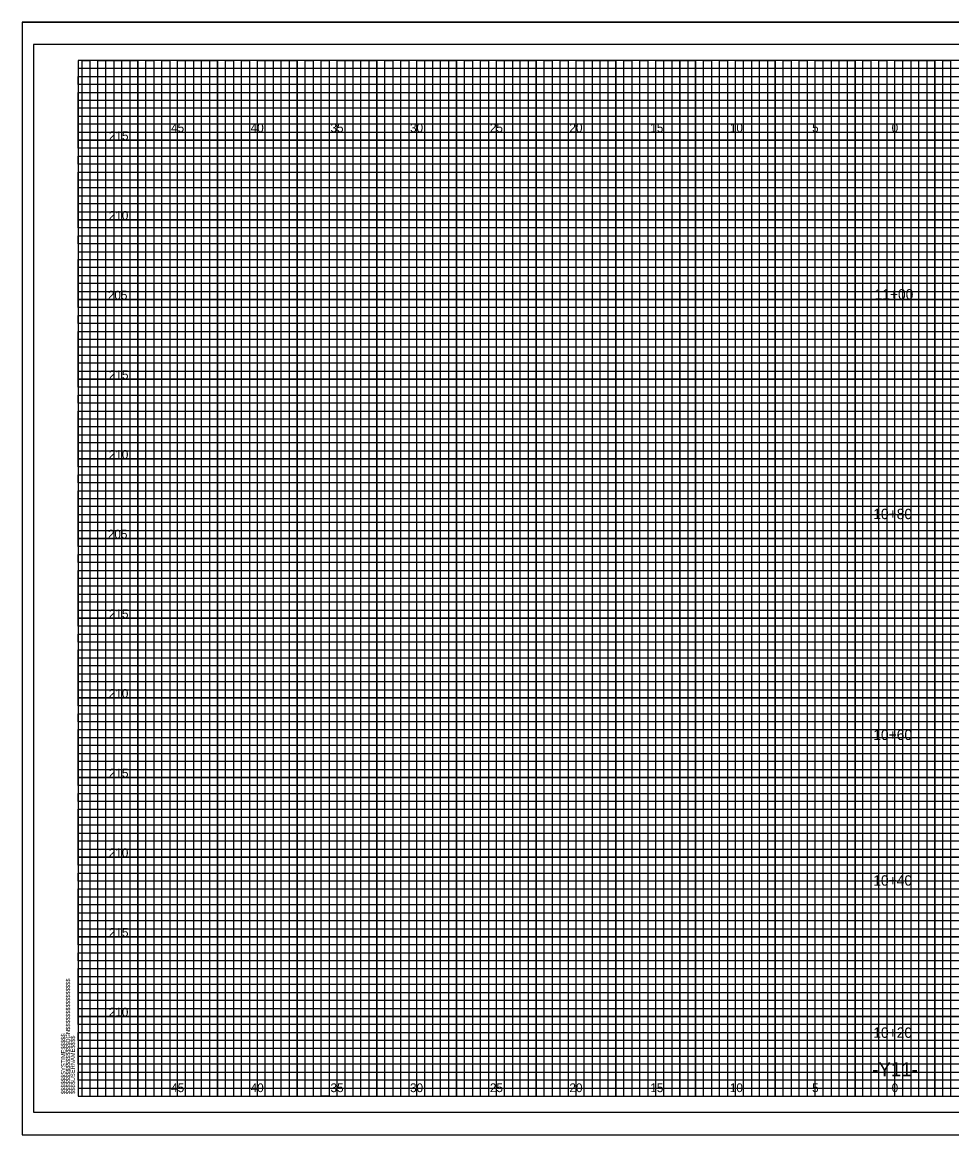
# Model space of a CAD drawing. Extents: x -4 to 103, y -2 to 67.
# Drawn here: x -3.5 to 54.8, y -2.4 to 67.4 of the extents above; entities that cross this region are included whole.
import ezdxf

# ---------------------------------------------------------------- set-up
doc = ezdxf.new("R2010")
doc.units = 0
for name, color, linetype in [('Old_Level_10', 7, 'Continuous'), ('Old_Level_16', 7, 'Continuous'), ('Old_Level_3', 7, 'Continuous'), ('Old_Level_5', 7, 'Continuous'), ('Old_Level_8', 7, 'Continuous'), ('Prop XS Dump Level', 7, 'Continuous'), ('Prop XS EOT Tick Mark', 7, 'Continuous'), ('Prop XS Finish Grade Pavement', 7, 'Continuous'), ('Prop XS Subgrade Concrete', 7, 'Continuous'), ('Prop XS Subgrade Earthwork', 7, 'Continuous'), ('Typical Curb CELL', 7, 'Continuous')]:
    doc.layers.add(name, color=color, linetype=linetype)

msp = doc.modelspace()

# ---------------------------------------------------------------- linework, layer by layer
at = {"layer": 'Old_Level_10'}
for p, q in [((1.25, 0), (1.25, 65)), ((3.75, 0), (3.75, 65)), ((6.25, 0), (6.25, 65)), ((8.75, 0), (8.75, 65)), ((11.25, 0), (11.25, 65)), ((13.75, 0), (13.75, 65)), ((16.25, 0), (16.25, 65)), ((18.75, 0), (18.75, 65)), ((21.25, 0), (21.25, 65)), ((23.75, 0), (23.75, 65)), ((26.25, 0), (26.25, 65)), ((28.75, 0), (28.75, 65)), ((31.25, 0), (31.25, 65)), ((33.75, 0), (33.75, 65)), ((36.25, 0), (36.25, 65)), ((38.75, 0), (38.75, 65)), ((41.25, 0), (41.25, 65)), ((43.75, 0), (43.75, 65)), ((46.25, 0), (46.25, 65)), ((48.75, 0), (48.75, 65)), ((51.25, 0), (51.25, 65)), ((53.75, 0), (53.75, 65)), ((0, 62.5), (74.25, 62.5)), ((0, 60), (102.5, 60)), ((0, 57.5), (102.5, 57.5)), ((0, 55), (102.5, 55)), ((0, 52.5), (102.5, 52.5)), ((0, 50), (102.5, 50)), ((0, 47.5), (102.5, 47.5)), ((0, 45), (102.5, 45)), ((0, 42.5), (102.5, 42.5)), ((0, 40), (102.5, 40)), ((0, 37.5), (102.5, 37.5)), ((0, 35), (102.5, 35)), ((0, 32.5), (102.5, 32.5)), ((0, 30), (102.5, 30)), ((0, 27.5), (102.5, 27.5)), ((0, 25), (102.5, 25)), ((0, 22.5), (102.5, 22.5)), ((0, 20), (102.5, 20)), ((0, 17.5), (102.5, 17.5)), ((0, 15), (102.5, 15)), ((0, 12.5), (102.5, 12.5)), ((0, 10), (102.5, 10)), ((0, 7.5), (102.5, 7.5)), ((0, 5), (102.5, 5)), ((0, 2.5), (102.5, 2.5))]:
    msp.add_line(p, q, dxfattribs=at)
at = {"layer": 'Old_Level_3'}
for p, q in [((-3.5, 67.4), (103.4, 67.4)), ((-3.5, 67.4), (-3.5, -2.425)), ((-3.5, -2.425), (103.4, -2.425))]:
    msp.add_line(p, q, dxfattribs=at)
at = {"layer": 'Old_Level_5'}
msp.add_lwpolyline([(103.4, 67.4), (-3.5, 67.4), (-3.5, -2.425), (103.4, -2.425)], close=True, dxfattribs=at)
at = {"layer": 'Old_Level_8'}
for points in [[(1.25, 0), (1.25, 65), (3.75, 65), (3.75, 0), (6.25, 0), (6.25, 65), (8.75, 65), (8.75, 0), (11.25, 0), (11.25, 65), (13.75, 65), (13.75, 0), (16.25, 0), (16.25, 65), (18.75, 65), (18.75, 0), (21.25, 0), (21.25, 65), (23.75, 65), (23.75, 0), (26.25, 0), (26.25, 65), (28.75, 65), (28.75, 0), (31.25, 0), (31.25, 65), (33.75, 65), (33.75, 0), (36.25, 0), (36.25, 65), (38.75, 65), (38.75, 0), (41.25, 0), (41.25, 65), (43.75, 65), (43.75, 0), (46.25, 0), (46.25, 65), (48.75, 65), (48.75, 0), (51.25, 0), (51.25, 65), (53.75, 65), (53.75, 0)], [(102.5, 60), (0, 60), (0, 62.5), (74.25, 62.5)], [(102.5, 55), (0, 55), (0, 57.5), (102.5, 57.5)], [(102.5, 50), (0, 50), (0, 52.5), (102.5, 52.5)], [(102.5, 45), (0, 45), (0, 47.5), (102.5, 47.5)], [(102.5, 40), (0, 40), (0, 42.5), (102.5, 42.5)], [(102.5, 35), (0, 35), (0, 37.5), (102.5, 37.5)], [(102.5, 30), (0, 30), (0, 32.5), (102.5, 32.5)], [(102.5, 25), (0, 25), (0, 27.5), (102.5, 27.5)], [(102.5, 20), (0, 20), (0, 22.5), (102.5, 22.5)], [(102.5, 15), (0, 15), (0, 17.5), (102.5, 17.5)], [(102.5, 10), (0, 10), (0, 12.5), (102.5, 12.5)], [(102.5, 5), (0, 5), (0, 7.5), (102.5, 7.5)], [(0, 2.5), (102.5, 2.5)]]:
    msp.add_lwpolyline(points, dxfattribs=at)
at = {"layer": 'Prop XS Dump Level'}
for points in [[(0.25, 0), (0.25, 65), (0.75, 65), (0.75, 0), (1.75, 0), (1.75, 65), (2.25, 65), (2.25, 0), (2.75, 0), (2.75, 65), (3.25, 65), (3.25, 0), (4.25, 0), (4.25, 65), (4.75, 65), (4.75, 0), (5.25, 0), (5.25, 65), (5.75, 65), (5.75, 0), (6.75, 0), (6.75, 65), (7.25, 65), (7.25, 0), (7.75, 0), (7.75, 65), (8.25, 65), (8.25, 0), (9.25, 0), (9.25, 65), (9.75, 65), (9.75, 0), (10.25, 0), (10.25, 65), (10.75, 65), (10.75, 0), (11.75, 0), (11.75, 65), (12.25, 65), (12.25, 0), (12.75, 0), (12.75, 65), (13.25, 65), (13.25, 0), (14.25, 0), (14.25, 65), (14.75, 65), (14.75, 0), (15.75, 0), (15.25, 0), (15.25, 65), (15.75, 65), (15.75, 0), (16.75, 0), (16.75, 65), (17.25, 65), (17.25, 0), (17.75, 0), (17.75, 65), (18.25, 65), (18.25, 0), (19.25, 0), (19.25, 65), (19.75, 65), (19.75, 0), (20.25, 0), (20.25, 65), (20.75, 65), (20.75, 0), (21.75, 0), (21.75, 65), (22.25, 65), (22.25, 0), (22.75, 0), (22.75, 65), (23.25, 65), (23.25, 0), (24.25, 0), (24.25, 65), (24.75, 65), (24.75, 0), (25.25, 0), (25.25, 65), (25.75, 65), (25.75, 0), (26.75, 0), (26.75, 65), (27.25, 65), (27.25, 0), (27.75, 0), (27.75, 65), (28.25, 65), (28.25, 0), (29.25, 0), (29.25, 65), (29.75, 65), (29.75, 0), (30.25, 0), (30.25, 65), (30.75, 65), (30.75, 0)], [(30.75, 0), (31.75, 0), (31.75, 65), (32.25, 65), (32.25, 0), (32.75, 0), (32.75, 65), (33.25, 65), (33.25, 0), (34.25, 0), (34.25, 65), (34.75, 65), (34.75, 0), (35.25, 0), (35.25, 65), (35.75, 65), (35.75, 0), (36.75, 0), (36.75, 65), (37.25, 65), (37.25, 0), (37.75, 0), (37.75, 65), (37.75, 0)], [(38.25, 65), (38.25, 0), (39.25, 0), (39.25, 65), (39.75, 65), (39.75, 0), (40.25, 0), (40.25, 65), (40.75, 65), (40.75, 0), (41.75, 0), (41.75, 65), (42.25, 65), (42.25, 0), (42.75, 0), (42.75, 65), (43.25, 65), (43.25, 0), (43.75, 0), (44.25, 0), (44.25, 65), (44.75, 65), (44.75, 0), (45.25, 0), (45.25, 65), (45.75, 65), (45.75, 0), (46.75, 0), (46.75, 65), (47.25, 65), (47.25, 0), (47.75, 0), (47.75, 65), (48.25, 65), (48.25, 0), (49.25, 0), (49.25, 65), (49.75, 65), (49.75, 0), (50.25, 0), (50.25, 65), (50.75, 65), (50.75, 0), (51.75, 0), (51.75, 65), (52.25, 65), (52.25, 0), (52.75, 0), (52.75, 65), (53.25, 65), (53.25, 0), (54.25, 0), (54.25, 65), (54.75, 65), (54.75, 0), (55.25, 0)], [(0, 62), (0, 63), (74.25, 63), (74.25, 63.5), (0, 63.5), (0, 64), (74.25, 64), (74.25, 64.5), (0, 64.5)], [(102.5, 62), (0, 62)], [(102.5, 61), (0, 61), (0, 61.5), (102.5, 61.5)], [(102.5, 59.5), (0, 59.5), (0, 60.5), (102.5, 60.5)], [(102.5, 58.5), (0, 58.5), (0, 59), (102.5, 59)], [(102.5, 57), (0, 57), (0, 58), (102.5, 58)], [(102.5, 56), (0, 56), (0, 56.5), (102.5, 56.5)], [(102.5, 54.5), (0, 54.5), (0, 55.5), (102.5, 55.5)], [(102.5, 53.5), (0, 53.5), (0, 54), (102.5, 54)], [(0, 53), (102.5, 53)], [(102.5, 52), (0, 52)], [(102.5, 51), (0, 51), (0, 51.5), (102.5, 51.5)], [(102.5, 49.5), (0, 49.5), (0, 50.5), (102.5, 50.5)], [(102.5, 48.5), (0, 48.5), (0, 49), (102.5, 49)], [(102.5, 47), (0, 47), (0, 48), (102.5, 48)], [(102.5, 46), (0, 46), (0, 46.5), (102.5, 46.5)], [(102.5, 44.5), (0, 44.5), (0, 45.5), (102.5, 45.5)], [(102.5, 43.5), (0, 43.5), (0, 44), (102.5, 44)], [(102.5, 42), (0, 42), (0, 43), (102.5, 43)], [(102.5, 41), (0, 41), (0, 41.5), (102.5, 41.5)], [(102.5, 39.5), (0, 39.5), (0, 40.5), (102.5, 40.5)], [(102.5, 38.5), (0, 38.5), (0, 39), (102.5, 39)], [(102.5, 37), (0, 37), (0, 38), (102.5, 38)], [(102.5, 36), (0, 36), (0, 36.5), (102.5, 36.5)], [(102.5, 34.5), (0, 34.5), (0, 35.5), (102.5, 35.5)], [(102.5, 33.5), (0, 33.5), (0, 34), (102.5, 34)], [(102.5, 32), (0, 32), (0, 33), (102.5, 33)], [(102.5, 31), (0, 31), (0, 31.5)], [(0, 31.5), (102.5, 31.5)], [(102.5, 29.5), (0, 29.5), (0, 30.5), (102.5, 30.5)], [(102.5, 28.5), (0, 28.5), (0, 29), (102.5, 29)], [(102.5, 27), (0, 27), (0, 28), (102.5, 28)], [(102.5, 26), (0, 26), (0, 26.5), (102.5, 26.5)], [(102.5, 24.5), (0, 24.5), (0, 25.5), (102.5, 25.5)], [(102.5, 23.5), (0, 23.5), (0, 24), (102.5, 24)], [(102.5, 22), (0, 22), (0, 23), (102.5, 23)], [(102.5, 21), (0, 21), (0, 21.5), (102.5, 21.5)], [(102.5, 19.5), (0, 19.5), (0, 20.5), (102.5, 20.5)], [(102.5, 18.5), (0, 18.5), (0, 19), (102.5, 19)], [(102.5, 17), (0, 17), (0, 18), (102.5, 18)], [(102.5, 16), (0, 16), (0, 16.5), (102.5, 16.5)], [(102.5, 14.5), (0, 14.5), (0, 15.5), (102.5, 15.5)], [(102.5, 13.5), (0, 13.5), (0, 14), (102.5, 14)], [(102.5, 12), (0, 12), (0, 13), (102.5, 13)], [(102.5, 11), (0, 11), (0, 11.5), (102.5, 11.5)], [(102.5, 9.5), (0, 9.5), (0, 10.5), (102.5, 10.5)], [(102.5, 8.5), (0, 8.5), (0, 9), (102.5, 9)], [(102.5, 7), (0, 7), (0, 8), (102.5, 8)], [(102.5, 6), (0, 6), (0, 6.5), (102.5, 6.5)], [(102.5, 4.5), (0, 4.5), (0, 5.5), (102.5, 5.5)], [(102.5, 3.5), (0, 3.5), (0, 4), (102.5, 4)], [(102.5, 2), (0, 2), (0, 3), (102.5, 3)], [(102.5, 1), (0, 1), (0, 1.5), (102.5, 1.5)], [(0, 0.5), (102.5, 0.5)]]:
    msp.add_lwpolyline(points, dxfattribs=at)
at = {"layer": 'Prop XS Subgrade Concrete'}
msp.add_lwpolyline([(102.5, 65), (0, 65), (0, 0), (102.5, 0)], close=True, dxfattribs=at)
at = {"layer": 'Typical Curb CELL'}
msp.add_lwpolyline([(103, 66), (-2.8, 66), (-2.8, -1), (103, -1)], close=True, dxfattribs=at)

# ---------------------------------------------------------------- texts
at = {"layer": 'Old_Level_16'}
for s, p in [('45', (5.8399, 60.5)), ('40', (10.8313, 60.5)), ('35', (15.8399, 60.5)), ('30', (20.8313, 60.5)), ('25', (25.8399, 60.5)), ('20', (30.8313, 60.5)), ('15', (35.9058, 60.5)), ('10', (40.8971, 60.5)), ('5', (46.0574, 60.5)), ('0', (51.0488, 60.5)), ('0', (51.0488, 60.5)), ('45', (5.8399, 0.25)), ('40', (10.8313, 0.25)), ('35', (15.8399, 0.25)), ('30', (20.8313, 0.25)), ('25', (25.8399, 0.25)), ('20', (30.8313, 0.25)), ('15', (35.9058, 0.25)), ('10', (40.8971, 0.25)), ('5', (46.0574, 0.25)), ('0', (51.0488, 0.25)), ('0', (51.0488, 0.25))]:
    msp.add_text(s, height=0.55, dxfattribs=at).set_placement(p)
at = {"layer": 'Old_Level_8'}
msp.add_text('040397', height=0.0025, rotation=90, dxfattribs=at).set_placement((-0.0007, 64.9864))
at = {"layer": 'Prop XS EOT Tick Mark'}
for s, p in [('215', (1.9383, 60)), ('210', (1.9296, 55)), ('205', (1.8724, 50)), ('215', (1.9383, 45)), ('210', (1.9296, 40)), ('205', (1.8724, 35)), ('215', (1.9383, 30)), ('210', (1.9296, 25)), ('215', (1.9383, 20)), ('210', (1.9296, 15)), ('215', (1.9383, 10)), ('210', (1.9296, 5))]:
    msp.add_text(s, height=0.55, dxfattribs=at).set_placement(p)
at = {"layer": 'Prop XS Finish Grade Pavement'}
for s, p in [('11+00', (49.9712, 49.9989)), ('10+80', (49.8934, 36.2128)), ('10+60', (49.8934, 22.352)), ('10+40', (49.8934, 13.21)), ('10+20', (49.8934, 3.6582))]:
    msp.add_text(s, height=0.65, dxfattribs=at).set_placement(p)
at = {"layer": 'Prop XS Subgrade Concrete'}
for s, p in [('$$$$$$$$$$$$$$$$DGN$$$$$$$$$$$$$$$$', (-0.5, 0.125)), ('$$$$$$SYSTIME$$$$$', (-0.7973, 0.1247)), ('$$$$USERNAME$$$$', (-0.2, 0.125))]:
    msp.add_text(s, height=0.2625, rotation=90, dxfattribs=at).set_placement(p)
at = {"layer": 'Prop XS Subgrade Earthwork'}
msp.add_text('-Y11-', height=0.875, dxfattribs=at).set_placement((49.8328, 1.25))

doc.saveas('drawing.dxf')
